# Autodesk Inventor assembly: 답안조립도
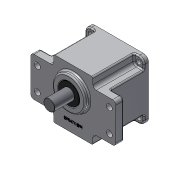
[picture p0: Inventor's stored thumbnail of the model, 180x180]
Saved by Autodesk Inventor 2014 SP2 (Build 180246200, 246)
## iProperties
Created: 2014-12
Part Number: 답안조립도
Document SubType Name: Assembly
Designer: 02
Author: 02
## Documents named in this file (12)
- C:\Users\02\Desktop\Inventor2급\답안조립품.iam
- C:\Users\02\Desktop\Inventor2급\1-본체.ipt
- C:\Users\02\Desktop\Inventor2급\2-커버.ipt
- C:\Users\02\Desktop\Inventor2급\메인축.ipt
- C:\Users\02\Desktop\Inventor2급\서브축.ipt
- C:\Users\02\Desktop\Inventor2급\베어링 608.ipt
- 베어링 608.ipt
- C:\Users\02\Desktop\Inventor2급\베어링 6003.ipt
- 베어링 6003.ipt
- C:\Users\02\Desktop\Inventor2급\오일실 17x32x8.ipt
- C:\Users\02\Desktop\Inventor2급\오일실 8x22x7.ipt
- C:\Users\02\Desktop\Inventor2급\M4x0.5x16.ipt
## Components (6 placed, 3 different names)
1. 1-본체:1 — 플러쉬:1, 플러쉬:2, 플러쉬:5
2. 2-커버:1 — 플러쉬:3, 플러쉬:4, 플러쉬:6
3. M4x0.5x12:1
4. M4x0.5x12:2
5. M4x0.5x12:3
6. M4x0.5x12:4
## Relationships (6: Flush 6)
- 플러쉬:1 [Flush]: 1-본체:1
- 플러쉬:2 [Flush]: 1-본체:1
- 플러쉬:3 [Flush]: 2-커버:1
- 플러쉬:4 [Flush]: 2-커버:1
- 플러쉬:5 [Flush]: 1-본체:1
- 플러쉬:6 [Flush]: 2-커버:1
